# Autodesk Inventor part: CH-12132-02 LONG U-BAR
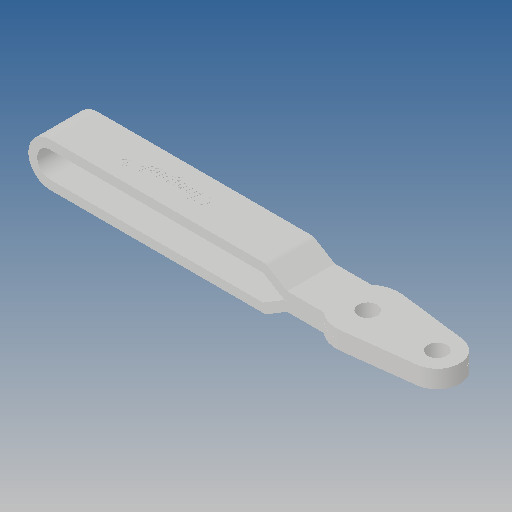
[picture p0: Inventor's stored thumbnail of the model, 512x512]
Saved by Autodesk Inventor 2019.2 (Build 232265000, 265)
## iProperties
Created: 2012-09
Part Number: CH-12132-02 LONG U-BAR
Material: Ogólny
Document SubType Name: Modeling
Designer: CADENGINEERING4
Density: 1 g/cm^3
Appearance: Domyślna
Author: CADENGINEERING4
Revision Number: ÈÎºÎ
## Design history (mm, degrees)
feature "ÇÐ³ý-À­Éì2"
feature "ÇÐ³ý-À­Éì6"
node "Bryła1"
node "Bryła2"
